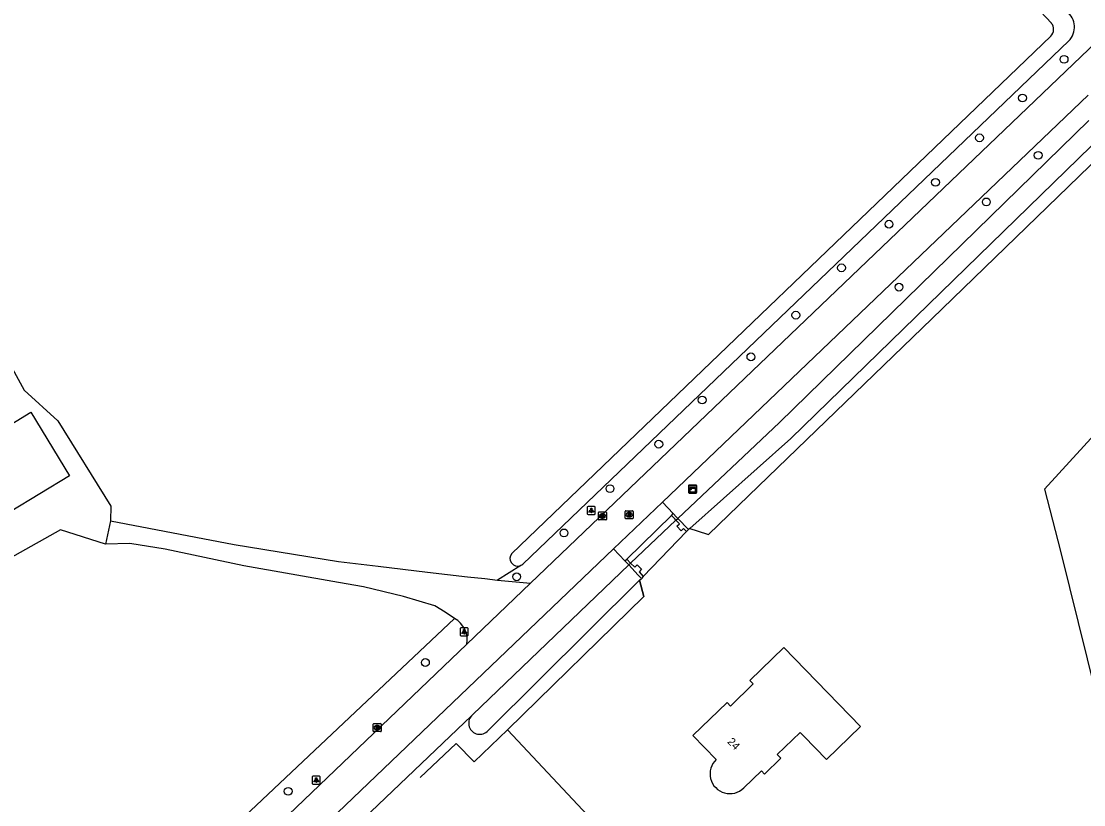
# Model space of a CAD drawing. Extents: x 157154 to 159278, y 385000 to 386650.
# Drawn here: x 157460.3 to 157593.2, y 385999.6 to 386097.5 of the extents above; entities that cross this region are included whole.
import ezdxf

# ---------------------------------------------------------------- set-up
doc = ezdxf.new("R2010")
doc.units = 0
for name, color, linetype in [('IMGEO_Boom', 7, 'Continuous'), ('IMGEO_Brandkraan', 7, 'Continuous'), ('IMGEO_Erf', 7, 'Continuous'), ('IMGEO_Gemengd_bos', 7, 'Continuous'), ('IMGEO_Grasland_overig', 7, 'Continuous'), ('IMGEO_Hek', 7, 'Continuous'), ('IMGEO_Inrit_open', 7, 'Continuous'), ('IMGEO_Kast', 7, 'Continuous'), ('IMGEO_Lichtpunt', 7, 'Continuous'), ('IMGEO_Loofbos', 7, 'Continuous'), ('IMGEO_Muur', 7, 'Continuous'), ('IMGEO_Pand', 7, 'Continuous'), ('IMGEO_Pand_nummerreeks', 7, 'Continuous'), ('IMGEO_Rijbaan_lokaal_halfverhard', 7, 'Continuous'), ('IMGEO_Rijbaan_lokaal_open', 7, 'Continuous'), ('IMGEO_Rioolput', 7, 'Continuous'), ('IMGEO_Waterloop', 7, 'Continuous')]:
    doc.layers.add(name, color=color, linetype=linetype)

msp = doc.modelspace()

# ---------------------------------------------------------------- linework, layer by layer
at = {"layer": 'IMGEO_Boom'}
for centre in [(157590.69, 386092.76), (157585.49, 386087.93), (157580.12, 386082.95), (157587.46, 386080.77), (157574.62, 386077.38), (157580.98, 386074.94), (157568.81, 386072.15), (157562.87, 386066.7), (157570.05, 386064.29), (157557.16, 386060.78), (157551.55, 386055.57), (157545.46, 386050.17), (157540.03, 386044.65), (157533.94, 386039.1), (157528.18, 386033.56), (157522.27, 386028.08), (157510.86, 386017.36), (157493.71, 386001.26)]:
    msp.add_circle(centre, 0.489, dxfattribs=at)
at = {"layer": 'IMGEO_Brandkraan'}
for p, q in [((157532.57, 386036.18), (157533.42, 386036.18)), ((157532.49, 386035.25), (157532.49, 386036.11)), ((157533.42, 386035.18), (157532.57, 386035.18)), ((157532.98, 386035.96), (157533.01, 386035.96)), ((157533, 386035.4), (157532.98, 386035.4)), ((157533.49, 386036.11), (157533.49, 386035.25)), ((157504.33, 386008.79), (157504.33, 386009.65)), ((157504.41, 386009.72), (157505.26, 386009.72)), ((157505.34, 386009.65), (157505.34, 386008.79)), ((157505.26, 386008.72), (157504.41, 386008.72)), ((157504.82, 386009.5), (157504.85, 386009.5)), ((157504.84, 386008.94), (157504.82, 386008.94))]:
    msp.add_line(p, q, dxfattribs=at)
for points in [[(157532.57, 386036.18), (157533.42, 386036.18)], [(157532.49, 386035.25), (157532.49, 386036.11)], [(157533.42, 386035.18), (157532.57, 386035.18)], [(157532.84, 386035.88), (157532.84, 386035.48), (157533.05, 386035.48)], [(157533.07, 386035.88), (157532.84, 386035.88)], [(157533.02, 386035.8), (157532.96, 386035.8), (157532.96, 386035.72)], [(157532.96, 386035.72), (157533.02, 386035.72)], [(157533.03, 386035.65), (157532.96, 386035.65), (157532.96, 386035.57)], [(157532.96, 386035.57), (157533.03, 386035.57)], [(157533.49, 386036.11), (157533.49, 386035.25)], [(157504.33, 386008.79), (157504.33, 386009.65)], [(157504.41, 386009.72), (157505.26, 386009.72)], [(157505.34, 386009.65), (157505.34, 386008.79)], [(157505.26, 386008.72), (157504.41, 386008.72)], [(157504.68, 386009.42), (157504.68, 386009.02), (157504.9, 386009.02)], [(157504.91, 386009.42), (157504.68, 386009.42)], [(157504.86, 386009.34), (157504.81, 386009.34), (157504.81, 386009.26)], [(157504.81, 386009.26), (157504.86, 386009.26)], [(157504.87, 386009.19), (157504.81, 386009.19), (157504.81, 386009.11)], [(157504.81, 386009.11), (157504.87, 386009.11)]]:
    msp.add_lwpolyline(points, dxfattribs=at)
for centre, radius, start, end in [((157532.57, 386036.1), 0.0765, 91.552, 178.448), ((157532.57, 386036.1), 0.0765, 91.552, 178.448), ((157533.42, 386036.1), 0.0765, 1.552, 88.448), ((157533.42, 386036.1), 0.0765, 1.552, 88.448), ((157532.57, 386035.26), 0.0765, 181.552, 268.448), ((157532.57, 386035.26), 0.0765, 181.552, 268.448), ((157533.02, 386035.76), 0.0379, 267.8285, 90.9355), ((157533.03, 386035.61), 0.0404, 269.8759, 90.5077), ((157533.06, 386035.73), 0.251, 268.6676, 293.5347), ((157533.08, 386035.73), 0.145, 59.4692, 91.5367), ((157533.1, 386035.78), 0.0922, 285.5137, 58.1501), ((157533.1, 386035.59), 0.105, 301.3115, 78.989), ((157533.42, 386035.26), 0.0765, 271.552, 358.448), ((157533.42, 386035.26), 0.0765, 271.552, 358.448), ((157504.41, 386009.65), 0.0765, 91.552, 178.448), ((157504.41, 386009.65), 0.0765, 91.552, 178.448), ((157505.26, 386009.65), 0.0765, 1.552, 88.448), ((157505.26, 386009.65), 0.0765, 1.552, 88.448), ((157504.41, 386008.8), 0.0765, 181.552, 268.448), ((157504.41, 386008.8), 0.0765, 181.552, 268.448), ((157504.86, 386009.3), 0.0379, 267.8285, 90.9355), ((157504.87, 386009.15), 0.0404, 269.8759, 90.5077), ((157504.9, 386009.27), 0.251, 268.6676, 293.5347), ((157504.92, 386009.28), 0.145, 59.4692, 91.5367), ((157504.94, 386009.32), 0.0922, 285.5137, 58.1501), ((157504.95, 386009.13), 0.105, 301.3115, 78.989), ((157505.26, 386008.8), 0.0765, 271.552, 358.448), ((157505.26, 386008.8), 0.0765, 271.552, 358.448)]:
    msp.add_arc(centre, radius, start, end, dxfattribs=at)
for centre, major_axis, ratio, start_param, end_param in [((157532.98, 386035.68), (-0.387, 0.002), 0.722429, 4.712389, 7.853982), ((157533, 386035.68), (-0.39, 0.002), 0.717154, 1.570796, 4.712389), ((157504.82, 386009.22), (-0.387, 0.002), 0.722429, 4.712389, 7.853982), ((157504.85, 386009.22), (-0.39, 0.002), 0.717154, 1.570796, 4.712389)]:
    msp.add_ellipse(centre, major_axis=major_axis, ratio=ratio, start_param=start_param, end_param=end_param, dxfattribs=at)
at = {"layer": 'IMGEO_Erf'}
for points in [[(157542.18, 386035.14), (157536.51, 386029.79)], [(157538.1, 386028.12), (157543.51, 386033.74)]]:
    msp.add_lwpolyline(points, dxfattribs=at)
at = {"layer": 'IMGEO_Gemengd_bos'}
msp.add_lwpolyline([(157543.9, 386034.12), (157544.83, 386033.82), (157546.23, 386033.37), (157552.49, 386039.41), (157574.16, 386060.33), (157597.82, 386083.26), (157600.88, 386083.37), (157618.6, 386072.25), (157588.24, 386039.03), (157590.26, 386031.28), (157597.98, 386000), (157598.9, 385996.27), (157574.27, 385974.36), (157562.9, 385964.41)], dxfattribs=at)
at = {"layer": 'IMGEO_Grasland_overig'}
for points in [[(157562.9, 385964.41), (157544.9, 385983.59), (157521.13, 386008.94), (157538.17, 386025.6), (157537.63, 386027.64)], [(157516.62, 386010.7), (157494.21, 385989.34)]]:
    msp.add_lwpolyline(points, dxfattribs=at)
at = {"layer": 'IMGEO_Hek'}
for points in [[(157543.9, 386034.12), (157544.83, 386033.82), (157546.23, 386033.37), (157552.49, 386039.41), (157574.16, 386060.33), (157597.82, 386083.26), (157600.88, 386083.37), (157618.6, 386072.25), (157588.24, 386039.03), (157590.26, 386031.28), (157597.98, 386000), (157598.9, 385996.27), (157574.27, 385974.36), (157562.9, 385964.41)], [(157537.63, 386027.64), (157538.17, 386025.6), (157521.13, 386008.94)], [(157510.22, 386003), (157514.7, 386007.25), (157516.95, 386004.96), (157521.13, 386008.94)], [(157521.13, 386008.94), (157544.9, 385983.59), (157562.9, 385964.41)]]:
    msp.add_lwpolyline(points, dxfattribs=at)
at = {"layer": 'IMGEO_Inrit_open'}
for points in [[(157471.52, 386035.08), (157470.89, 386032.16)], [(157471.52, 386035.08), (157486.96, 386032.1), (157500, 386029.98), (157504.95, 386029.42), (157511.11, 386028.64), (157516.12, 386028.09), (157518.28, 386027.87), (157519.88, 386027.67)], [(157514.49, 386022.88), (157513.32, 386023.65), (157512.05, 386024.46), (157508.13, 386025.63), (157503.12, 386026.83), (157500, 386027.38), (157488.17, 386029.45), (157478.32, 386031.51), (157473.92, 386032.25), (157470.89, 386032.16)], [(157519.88, 386027.67), (157524, 386027.27)]]:
    msp.add_lwpolyline(points, dxfattribs=at)
msp.add_arc((157513.04, 386020.2), 3.05, 349.5619, 61.5066, dxfattribs=at)
at = {"layer": 'IMGEO_Kast'}
for p, q in [((157543.77, 386038.62), (157543.77, 386039.46)), ((157543.77, 386039.46), (157543.77, 386038.62)), ((157543.84, 386039.54), (157544.68, 386039.54)), ((157544.68, 386039.54), (157543.84, 386039.54)), ((157544.76, 386039.47), (157544.76, 386038.63)), ((157544.76, 386038.63), (157544.76, 386039.47)), ((157544.69, 386038.54), (157543.85, 386038.54)), ((157543.85, 386038.54), (157544.69, 386038.54))]:
    msp.add_line(p, q, dxfattribs=at)
for points in [[(157543.96, 386039.33), (157544.56, 386039.33), (157544.56, 386039.25), (157543.96, 386039.25), (157543.96, 386039.33)], [(157543.96, 386039.16), (157544.56, 386039.16), (157544.56, 386038.67), (157543.96, 386038.67), (157543.96, 386039.16)]]:
    msp.add_lwpolyline(points, dxfattribs=at)
msp.add_circle((157544.04, 386039), 0.0377, dxfattribs=at)
for centre, start, end in [((157543.84, 386039.46), 92.4484, 184.2845), ((157543.84, 386039.46), 92.4484, 184.2845), ((157544.69, 386039.46), 2.4484, 94.2845), ((157544.69, 386039.46), 2.4484, 94.2845), ((157543.84, 386038.62), 182.4484, 274.2845), ((157543.84, 386038.62), 182.4484, 274.2845), ((157544.69, 386038.62), 272.4484, 4.2845), ((157544.69, 386038.62), 272.4484, 4.2845)]:
    msp.add_arc(centre, 0.0779, start, end, dxfattribs=at)
at = {"layer": 'IMGEO_Lichtpunt'}
for p, q in [((157531.1, 386036.77), (157531.1, 386035.96)), ((157531.1, 386036.77), (157531.1, 386035.96)), ((157532, 386036.86), (157531.19, 386036.86)), ((157532, 386036.86), (157531.19, 386036.86)), ((157532.1, 386035.96), (157532.1, 386036.77)), ((157532.1, 386035.96), (157532.1, 386036.77)), ((157531.19, 386035.87), (157532, 386035.87)), ((157531.19, 386035.87), (157532, 386035.87)), ((157515.21, 386021.6), (157515.21, 386020.8)), ((157515.21, 386021.6), (157515.21, 386020.8)), ((157516.11, 386021.7), (157515.31, 386021.7)), ((157516.11, 386021.7), (157515.31, 386021.7)), ((157516.21, 386020.8), (157516.21, 386021.6)), ((157516.21, 386020.8), (157516.21, 386021.6)), ((157515.31, 386020.7), (157516.11, 386020.7)), ((157515.31, 386020.7), (157516.11, 386020.7)), ((157496.71, 386003.06), (157496.71, 386002.25)), ((157496.71, 386003.06), (157496.71, 386002.25)), ((157497.61, 386003.16), (157496.8, 386003.16)), ((157497.61, 386003.16), (157496.8, 386003.16)), ((157497.71, 386002.25), (157497.71, 386003.06)), ((157497.71, 386002.25), (157497.71, 386003.06)), ((157496.8, 386002.16), (157497.61, 386002.16)), ((157496.8, 386002.16), (157497.61, 386002.16))]:
    msp.add_line(p, q, dxfattribs=at)
for points in [[(157531.47, 386036.43), (157531.51, 386036.4), (157531.32, 386036.14), (157531.29, 386036.17), (157531.47, 386036.43)], [(157531.57, 386036.38), (157531.62, 386036.38), (157531.62, 386036.06), (157531.57, 386036.06), (157531.57, 386036.38)], [(157531.68, 386036.4), (157531.72, 386036.43), (157531.91, 386036.17), (157531.87, 386036.14), (157531.68, 386036.4)], [(157515.59, 386021.27), (157515.62, 386021.24), (157515.44, 386020.98), (157515.4, 386021), (157515.59, 386021.27)], [(157515.69, 386021.22), (157515.73, 386021.22), (157515.73, 386020.9), (157515.69, 386020.9), (157515.69, 386021.22)], [(157515.8, 386021.24), (157515.84, 386021.27), (157516.02, 386021), (157515.98, 386020.98), (157515.8, 386021.24)], [(157497.08, 386002.72), (157497.12, 386002.7), (157496.94, 386002.43), (157496.9, 386002.46), (157497.08, 386002.72)], [(157497.19, 386002.68), (157497.23, 386002.68), (157497.23, 386002.35), (157497.19, 386002.35), (157497.19, 386002.68)], [(157497.3, 386002.7), (157497.33, 386002.72), (157497.52, 386002.46), (157497.48, 386002.43), (157497.3, 386002.7)]]:
    msp.add_lwpolyline(points, dxfattribs=at)
for centre in [(157531.6, 386036.57), (157515.71, 386021.4), (157497.21, 386002.86)]:
    msp.add_circle(centre, 0.0994, dxfattribs=at)
for centre, start, end in [((157531.19, 386036.77), 90, 180), ((157531.19, 386036.77), 90, 180), ((157532, 386036.77), 0, 90), ((157532, 386036.77), 0, 90), ((157531.19, 386035.96), 180, 270), ((157531.19, 386035.96), 180, 270), ((157532, 386035.96), 270, 0), ((157532, 386035.96), 270, 360), ((157515.31, 386021.6), 90, 180), ((157515.31, 386021.6), 90, 180), ((157516.11, 386021.6), 0, 90), ((157516.11, 386021.6), 0, 90), ((157515.31, 386020.8), 180, 270), ((157515.31, 386020.8), 180, 270), ((157516.11, 386020.8), 270, 0), ((157516.11, 386020.8), 270, 360), ((157496.8, 386003.06), 90, 180), ((157496.8, 386003.06), 90, 180), ((157497.61, 386003.06), 0, 90), ((157497.61, 386003.06), 0, 90), ((157496.8, 386002.25), 180, 270), ((157496.8, 386002.25), 180, 270), ((157497.61, 386002.25), 270, 0), ((157497.61, 386002.25), 270, 360)]:
    msp.add_arc(centre, 0.0946, start, end, dxfattribs=at)
at = {"layer": 'IMGEO_Loofbos'}
for points in [[(157432.54, 386069), (157432.1, 386070.21), (157446.73, 386077.04), (157460.69, 386051.4), (157464.93, 386047.56), (157471.54, 386036.91), (157471.52, 386035.08)], [(157470.89, 386032.16), (157465.26, 386033.93), (157453.79, 386027.52), (157455.64, 386023.55), (157449.19, 386017.95), (157443.83, 386022.67), (157442.74, 386023.19), (157441.67, 386024.45), (157439.64, 386028.24), (157438.12, 386030.34), (157436.21, 386031.99), (157434.42, 386033.23), (157433.26, 386035.33), (157431.83, 386038.65), (157420.32, 386034.26), (157417.3, 386041.54), (157426.49, 386045.26), (157424.54, 386049.8), (157429.7, 386052.02), (157431.65, 386047.47), (157433.87, 386048.42), (157426.2, 386066.3), (157427.08, 386066.69)], [(157522.77, 386029.5), (157519.88, 386027.67)], [(157468.65, 385978.5), (157470, 385981.06), (157480.25, 385990.59), (157514.49, 386022.88)]]:
    msp.add_lwpolyline(points, dxfattribs=at)
at = {"layer": 'IMGEO_Muur'}
for points in [[(157541.61, 386035.74), (157541.83, 386035.98)], [(157542.18, 386035.14), (157542.03, 386035.31), (157541.61, 386035.74)], [(157541.83, 386035.98), (157542.24, 386035.55), (157542.42, 386035.37)], [(157542.18, 386035.14), (157542.42, 386035.37)], [(157543.51, 386033.74), (157543.13, 386034.12), (157542.83, 386033.84), (157542.3, 386034.39), (157542.62, 386034.68), (157542.18, 386035.14)], [(157542.42, 386035.37), (157543.75, 386033.98)], [(157543.75, 386033.98), (157543.51, 386033.74)], [(157535.79, 386030.09), (157536.02, 386030.3)], [(157536.27, 386029.57), (157535.79, 386030.09)], [(157536.02, 386030.3), (157536.51, 386029.79)], [(157536.51, 386029.79), (157536.27, 386029.57)], [(157537.86, 386027.87), (157537.46, 386028.29), (157536.27, 386029.57)], [(157536.51, 386029.79), (157537.02, 386029.26), (157537.33, 386029.57), (157537.86, 386029.02), (157537.58, 386028.68), (157538.1, 386028.12)], [(157538.1, 386028.12), (157537.86, 386027.87)]]:
    msp.add_lwpolyline(points, dxfattribs=at)
at = {"layer": 'IMGEO_Pand'}
for points in [[(157451.5, 386031.69), (157449.35, 386035.24), (157442.01, 386030.8), (157437.03, 386039.02), (157453.13, 386048.77), (157455.44, 386044.95), (157461.55, 386048.65), (157466.37, 386040.7), (157451.5, 386031.69)], [(157550.66, 386001.68), (157552.86, 386003.81), (157553.25, 386003.42), (157555.29, 386005.4), (157554.84, 386005.86), (157557.71, 386008.63), (157558.16, 386008.16), (157560.98, 386005.24), (157565.24, 386009.36), (157555.67, 386019.22), (157551.42, 386015.11), (157551.84, 386014.68), (157548.99, 386011.91), (157548.57, 386012.35), (157544.3, 386008.23), (157547.21, 386005.23)]]:
    msp.add_lwpolyline(points, dxfattribs=at)
msp.add_arc((157548.92, 386003.45), 2.48, 133.8228, 314.6057, dxfattribs=at)
at = {"layer": 'IMGEO_Rijbaan_lokaal_halfverhard'}
for points in [[(157541.83, 386035.98), (157540.48, 386037.39)], [(157541.61, 386035.74), (157536.02, 386030.3)], [(157534.38, 386031.56), (157535.79, 386030.09)]]:
    msp.add_lwpolyline(points, dxfattribs=at)
at = {"layer": 'IMGEO_Rijbaan_lokaal_open'}
for points in [[(157524, 386027.27), (157595.68, 386095.83)], [(157540.48, 386037.39), (157593.7, 386088.29)], [(157534.38, 386031.56), (157540.48, 386037.39)], [(157492.25, 385991.28), (157534.38, 386031.56)], [(157516.04, 386019.65), (157524, 386027.27)], [(157516.04, 386019.65), (157438.46, 385945.46), (157436.42, 385943.53), (157433.81, 385941.48), (157433.37, 385941.16)]]:
    msp.add_lwpolyline(points, dxfattribs=at)
at = {"layer": 'IMGEO_Rioolput'}
for p, q in [((157535.83, 386035.4), (157535.83, 386036.25)), ((157535.9, 386036.33), (157536.76, 386036.33)), ((157536.83, 386036.25), (157536.83, 386035.4)), ((157536.76, 386035.33), (157535.9, 386035.33)), ((157536.34, 386035.55), (157536.31, 386035.55)), ((157536.32, 386036.11), (157536.34, 386036.11))]:
    msp.add_line(p, q, dxfattribs=at)
for points in [[(157535.83, 386035.4), (157535.83, 386036.25)], [(157535.9, 386036.33), (157536.76, 386036.33)], [(157536.83, 386036.25), (157536.83, 386035.4)], [(157536.76, 386035.33), (157535.9, 386035.33)], [(157536.42, 386036.02), (157536.17, 386036.03), (157536.17, 386035.63)], [(157536.17, 386035.63), (157536.29, 386035.63), (157536.29, 386035.79), (157536.3, 386035.79)], [(157536.34, 386035.95), (157536.29, 386035.95), (157536.29, 386035.86)], [(157536.29, 386035.86), (157536.34, 386035.86)], [(157536.35, 386035.76), (157536.42, 386035.63), (157536.56, 386035.63), (157536.49, 386035.75)]]:
    msp.add_lwpolyline(points, dxfattribs=at)
for centre, radius, start, end in [((157535.91, 386036.25), 0.0765, 91.552, 178.448), ((157535.91, 386036.25), 0.0765, 91.552, 178.448), ((157536.75, 386036.25), 0.0765, 1.552, 88.448), ((157536.75, 386036.25), 0.0765, 1.552, 88.448), ((157535.91, 386035.4), 0.0765, 181.552, 268.448), ((157535.91, 386035.4), 0.0765, 181.552, 268.448), ((157536.3, 386035.74), 0.0533, 26.0293, 88.6989), ((157536.35, 386035.85), 0.0964, 77.0061, 93.1865), ((157536.33, 386036.05), 0.19, 274.7715, 282.9687), ((157536.36, 386035.91), 0.0378, 276.6634, 79.6772), ((157536.42, 386035.92), 0.109, 350.3612, 89.416), ((157536.42, 386035.91), 0.112, 277.5842, 350.9817), ((157536.4, 386035.7), 0.108, 29.5134, 73.7905), ((157536.75, 386035.4), 0.0765, 271.552, 358.448), ((157536.75, 386035.4), 0.0765, 271.552, 358.448)]:
    msp.add_arc(centre, radius, start, end, dxfattribs=at)
for centre, major_axis, ratio, start_param, end_param in [((157536.32, 386035.83), (-0.387, 0.002), 0.722429, 4.712389, 7.853982), ((157536.34, 386035.83), (-0.39, 0.002), 0.717154, 1.570796, 4.712389)]:
    msp.add_ellipse(centre, major_axis=major_axis, ratio=ratio, start_param=start_param, end_param=end_param, dxfattribs=at)
at = {"layer": 'IMGEO_Waterloop'}
for points in [[(157589.1, 386097.3), (157529.15, 386160.84), (157500, 386191.98), (157476.97, 386216.58), (157472.14, 386221.23), (157465.7, 386226.89)], [(157521.65, 386030.99), (157589.03, 386095.65)], [(157591.3, 386095.06), (157523.02, 386029.66)], [(157542.42, 386035.37), (157555.14, 386047.38), (157593.8, 386085.13)], [(157595.6, 386083.39), (157556.52, 386045.35), (157543.9, 386034.12)], [(157543.9, 386034.12), (157543.75, 386033.98)], [(157536.27, 386029.57), (157516.79, 386010.86)], [(157537.63, 386027.64), (157518.69, 386008.87)], [(157537.63, 386027.64), (157537.86, 386027.87)]]:
    msp.add_lwpolyline(points, dxfattribs=at)
for centre, radius, start, end in [((157589.42, 386096.8), 2.56, 317.1628, 49.8625), ((157588.2, 386096.51), 1.19, 313.6608, 41.4865), ((157522.39, 386030.38), 0.958, 140.2972, 293.295), ((157522.37, 386030.41), 0.99, 293.5237, 311.1285), ((157517.65, 386009.77), 1.38, 138.1284, 318.9492), ((157517.55, 386009.88), 1.24, 127.8047, 138.7654)]:
    msp.add_arc(centre, radius, start, end, dxfattribs=at)

# ---------------------------------------------------------------- texts
at = {"layer": 'IMGEO_Pand_nummerreeks'}
msp.add_text('24', height=1, rotation=314.0774, dxfattribs=at).set_placement((157548.53, 386007.39))

doc.saveas('drawing.dxf')
